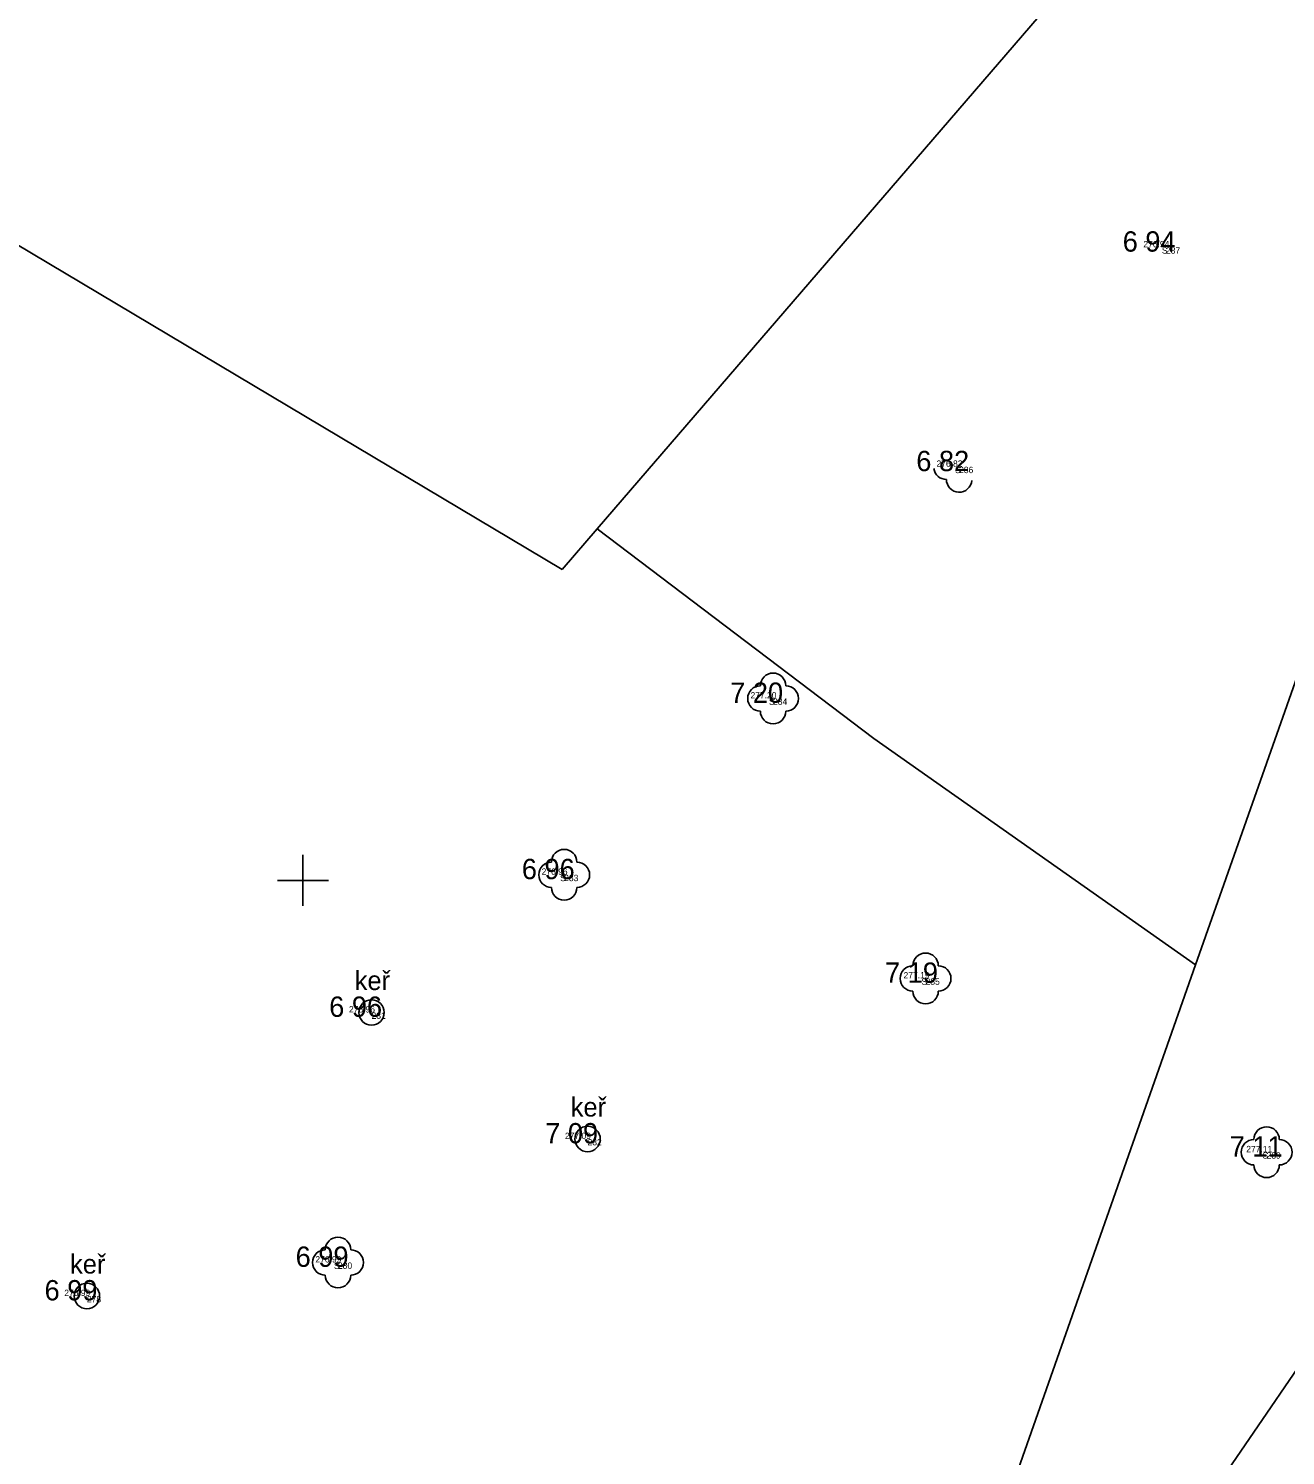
# Model space of a CAD drawing. Extents: x -601602 to -600882, y -1162594 to -1161950.
# Drawn here: x -601255.4 to -601230.67, y -1162061.32 to -1162033.24 of the extents above; entities that cross this region are included whole.
import ezdxf

# ---------------------------------------------------------------- set-up
doc = ezdxf.new("R2010")
doc.units = 0
for name, color, linetype in [('BODY', 7, 'Continuous'), ('BODY_CISLA', 7, 'Continuous'), ('BODY_KODY', 7, 'Continuous'), ('BODY_VYSKY_CELE', 7, 'Continuous'), ('G_TEXTY', 7, 'Continuous'), ('G_ZELEN', 7, 'Continuous'), ('H_KOTY_VYSKOVE', 7, 'Continuous'), ('KN_Hranice parcel', 7, 'Continuous'), ('X_SOUR_KRIZKY_SEVER', 7, 'Continuous')]:
    doc.layers.add(name, color=color, linetype=linetype)

# ---------------------------------------------------------------- blocks, each defined once
blk = doc.blocks.new('POINT_DISPLAY')
blk.add_line((0, 0), (0, 0))

msp = doc.modelspace()

# ---------------------------------------------------------------- linework, layer by layer
at = {"layer": 'G_ZELEN'}
for centre, radius in [((-601240.75, -1162046.42), 0.00025), ((-601244.86, -1162049.89), 0.00025), ((-601237.75, -1162051.93), 0.00025), ((-601248.65, -1162052.6), 0.25), ((-601244.4, -1162055.09), 0.25), ((-601231.04, -1162055.35), 0.00025), ((-601249.31, -1162057.52), 0.00025), ((-601254.25, -1162058.18), 0.25)]:
    msp.add_circle(centre, radius, dxfattribs=at)
for centre, start, end in [((-601237.34, -1162041.86), 188.346, 270), ((-601237.09, -1162042.11), 180, 355.7631), ((-601240.75, -1162046.17), 0, 180), ((-601241, -1162046.42), 90, 270), ((-601240.5, -1162046.42), 270, 90), ((-601240.75, -1162046.67), 180, 360), ((-601244.86, -1162049.64), 0, 180), ((-601245.11, -1162049.89), 90, 270), ((-601244.61, -1162049.89), 270, 90), ((-601244.86, -1162050.14), 180, 360), ((-601237.75, -1162051.68), 0, 180), ((-601238, -1162051.93), 90, 270), ((-601237.5, -1162051.93), 270, 90), ((-601237.75, -1162052.18), 180, 360), ((-601231.04, -1162055.1), 0, 180), ((-601231.29, -1162055.35), 90, 270), ((-601230.79, -1162055.35), 270, 90), ((-601231.04, -1162055.6), 180, 360), ((-601249.31, -1162057.27), 0, 180), ((-601249.56, -1162057.52), 90, 270), ((-601249.06, -1162057.52), 270, 90), ((-601249.31, -1162057.77), 180, 360)]:
    msp.add_arc(centre, 0.25, start, end, dxfattribs=at)
at = {"layer": 'KN_Hranice parcel'}
for p, q in [((-601232.03, -1162028.94), (-601244.21, -1162043.08)), ((-601244.9, -1162043.88), (-601266.06, -1162031.27)), ((-601232.44, -1162051.66), (-601228.82, -1162041.38)), ((-601244.21, -1162043.08), (-601244.9, -1162043.88)), ((-601232.44, -1162051.66), (-601238.38, -1162068.56))]:
    msp.add_line(p, q, dxfattribs=at)
for points in [[(-601232.44, -1162051.66), (-601238.77, -1162047.21), (-601244.21, -1162043.08)], [(-601221.67, -1162046.41), (-601229.23, -1162057.85), (-601232.4, -1162062.48), (-601235.5, -1162068.38), (-601235.8, -1162069.05), (-601236.91, -1162071.54), (-601237.28, -1162072.25), (-601237.73, -1162072.9), (-601238.31, -1162073.49), (-601238.42, -1162073.58), (-601238.93, -1162074), (-601239.44, -1162074.3), (-601240.59, -1162074.86)]]:
    msp.add_lwpolyline(points, dxfattribs=at)
at = {"layer": 'X_SOUR_KRIZKY_SEVER'}
for p, q in [((-601250, -1162050.5), (-601250, -1162049.5)), ((-601250.5, -1162050), (-601249.5, -1162050))]:
    msp.add_line(p, q, dxfattribs=at)

# ---------------------------------------------------------------- block references
at = {"layer": 'BODY'}
for p in [(-601233.02, -1162037.54), (-601237.09, -1162041.86), (-601240.75, -1162046.42), (-601244.86, -1162049.89), (-601237.75, -1162051.93), (-601248.65, -1162052.6), (-601244.4, -1162055.09), (-601231.04, -1162055.35), (-601249.31, -1162057.52), (-601254.25, -1162058.18)]:
    msp.add_blockref('POINT_DISPLAY', p, dxfattribs=at)

# ---------------------------------------------------------------- texts
at = {"layer": 'BODY_CISLA'}
for s, p in [('287', (-601233.02, -1162037.665)), ('286', (-601237.09, -1162041.985)), ('284', (-601240.75, -1162046.545)), ('283', (-601244.86, -1162050.015)), ('285', (-601237.75, -1162052.055)), ('281', (-601248.65, -1162052.725)), ('282', (-601244.4, -1162055.215)), ('289', (-601231.04, -1162055.475)), ('280', (-601249.31, -1162057.645)), ('278', (-601254.25, -1162058.305))]:
    msp.add_text(s, height=0.125, dxfattribs=at).set_placement(p)
at = {"layer": 'BODY_KODY'}
for p in [(-601233.101, -1162037.665), (-601237.171, -1162041.985), (-601240.831, -1162046.545), (-601244.941, -1162050.015), (-601237.831, -1162052.055), (-601231.121, -1162055.475), (-601249.391, -1162057.645)]:
    msp.add_text('S', height=0.125, dxfattribs=at).set_placement(p)
at = {"layer": 'BODY_VYSKY_CELE'}
for s, p in [('276.94 ', (-601233.465, -1162037.54)), ('276.82 ', (-601237.535, -1162041.86)), ('277.20 ', (-601241.195, -1162046.42)), ('276.96 ', (-601245.304, -1162049.89)), ('277.19 ', (-601238.184, -1162051.93)), ('276.96 ', (-601249.094, -1162052.6)), ('277.09 ', (-601244.845, -1162055.09)), ('277.11 ', (-601231.44, -1162055.35)), ('276.99 ', (-601249.755, -1162057.52)), ('276.99 ', (-601254.695, -1162058.18))]:
    msp.add_text(s, height=0.125, dxfattribs=at).set_placement(p)
at = {"layer": 'G_TEXTY'}
for p in [(-601248.982, -1162052.158), (-601244.732, -1162054.648), (-601254.582, -1162057.738)]:
    msp.add_text('keř', height=0.375, dxfattribs=at).set_placement(p)
at = {"layer": 'H_KOTY_VYSKOVE'}
for s, p in [(' 6 94', (-601234.02, -1162037.626)), (' 6 82', (-601238.081, -1162041.946)), (' 7 20', (-601241.743, -1162046.506)), (' 6 96', (-601245.842, -1162049.976)), (' 7 19', (-601238.696, -1162052.016)), (' 6 96', (-601249.632, -1162052.686)), (' 7 09', (-601245.382, -1162055.176)), (' 7 11', (-601231.915, -1162055.436)), (' 6 99', (-601250.292, -1162057.606)), (' 6 99', (-601255.232, -1162058.266))]:
    msp.add_text(s, height=0.4, dxfattribs=at).set_placement(p)

doc.saveas('drawing.dxf')
